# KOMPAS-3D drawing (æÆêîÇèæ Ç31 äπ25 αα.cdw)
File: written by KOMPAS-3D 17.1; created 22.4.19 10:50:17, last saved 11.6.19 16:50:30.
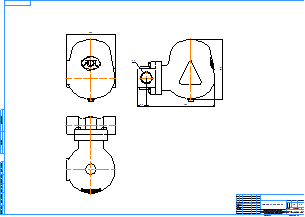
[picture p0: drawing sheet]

Sheet 1: A1, landscape

Title block, sheet 1: name: СТИМАКС А31 Ду25 рр; material: Внимание! Данный продукт является объектом авторского права ООО «Торговый Дом АДЛ». / Запрещается изменение, копирование, распространение / (в том числе путем копирования на другие сайты и ресурсы в Интернете) / или любое иное использование информации и объектов без предварительного / согласия правообладателя (ООО «Торговый Дом АДЛ»).; mass: 7,5; sheets: 1; organisation: ООО "Торговый дом АДЛ"; sheet format: A1; stored path: \\adlc.lan\data\АДЛ_ПКД\3D-модели\ADL production\Конденсатоотводчики СТИМАКС\Поплавковые\Серия А31\KOMPAS 2D\СТИМАКС А31 Ду25 рр.cdw

Views: Вид 1, Проекционный вид 2, Проекционный вид 3
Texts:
  user
Dimensions and other numbers on the sheet: 135; 25; 186; 164; 1:1; 1; 7,5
